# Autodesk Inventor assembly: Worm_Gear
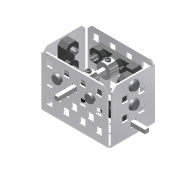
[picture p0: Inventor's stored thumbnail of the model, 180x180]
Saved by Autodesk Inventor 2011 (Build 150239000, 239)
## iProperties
Created: 2008-05
Part Number: Worm_Gear
Document SubType Name: Assembly
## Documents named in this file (8)
- C:\Data Folder\VEX 2011\Inventor Datasets\Unit 9\Worm_Gear.iam
- C:\Data Folder\VEX 2011\Inventor Datasets\Unit 9\Components\VL-WORM-BRK RevA.ipt
- C:\Data Folder\VEX 2011\Inventor Datasets\Unit 9\Components\BEARING-FLAT.ipt
- C:\Data Folder\VEX 2011\Inventor Datasets\Unit 9\Components\BEARING-RIVET.ipt
- C:\Data Folder\VEX 2011\Inventor Datasets\Unit 9\Components\Shaft_Collar.iam
- C:\Data Folder\VEX 2011\Inventor Datasets\Unit 9\Components\SHAFT-2000.ipt
- C:\Data Folder\VEX 2011\Inventor Datasets\Unit 9\Components\SHAFT-3000.ipt
- C:\Data Folder\VEX 2011\Inventor Datasets\Unit 9\Components\SPACER-THIN.ipt
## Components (22 placed, 7 different names)
1. VL-WORM-BRK RevA:1 — Mate:1, Mate:2, Mate:3, Mate:4, Mate:5, Mate:6, Mate:7, Mate:8, Mate:9, Mate:10, Mate:11, Mate:12, Flush:1, Flush:2, Flush:3, Flush:4, Flush:5, Flush:6, Flush:7, Flush:8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
2. BEARING-FLAT:1 — Mate:1, Mate:2, Mate:3, Mate:13, Mate:14, Mate:27
3. BEARING-FLAT:2 — Mate:4, Mate:5, Mate:6, Mate:15, Mate:16, Mate:25, Mate:31
4. BEARING-FLAT:3 — Mate:7, Mate:8, Mate:9, Mate:17, Mate:18, Mate:21, Mate:24
5. BEARING-FLAT:4 — Mate:10, Mate:11, Mate:12, Mate:19, Mate:20
6. BEARING-RIVET:1 — Mate:13, Flush:1
7. BEARING-RIVET:2 — Mate:14, Flush:2
8. BEARING-RIVET:3 — Mate:17, Flush:5
9. BEARING-RIVET:4 — Mate:18, Flush:6
10. BEARING-RIVET:5 — Mate:15, Flush:3
11. BEARING-RIVET:6 — Mate:16, Flush:4
12. BEARING-RIVET:7 — Mate:19, Flush:7
13. BEARING-RIVET:8 — Mate:20, Flush:8
14. Shaft_Collar:1 [sub-assembly] — Mate:22, Angle:2
15. SHAFT-2000:1 — Mate:21, Flush:9, Angle:1, Mate:22, Mate:23
16. Shaft_Collar:2 [sub-assembly] — Mate:23, Angle:3, Mate:24, Angle:4
17. Shaft_Collar:4 [sub-assembly] — Mate:26, Mate:27, Angle:6, Mate:30
18. SHAFT-3000:1 — Mate:25, Flush:10, Angle:5, Mate:26, Mate:28, Mate:29, Mate:33, Mate:34
19. SPACER-THIN:1 — Mate:28, Mate:31, Mate:35
20. SPACER-THIN:2 — Mate:29, Mate:30
21. SPACER-THIN:3 — Mate:34, Mate:35, Mate:36
22. SPACER-THIN:4 — Mate:33, Mate:36
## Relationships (51: Mate 35, Flush 10, Angle 6)
- Mate:1: VL-WORM-BRK RevA:1 ↔ BEARING-FLAT:1
- Mate:2: VL-WORM-BRK RevA:1 ↔ BEARING-FLAT:1
- Mate:3: VL-WORM-BRK RevA:1 ↔ BEARING-FLAT:1
- Mate:4: VL-WORM-BRK RevA:1 ↔ BEARING-FLAT:2
- Mate:5: VL-WORM-BRK RevA:1 ↔ BEARING-FLAT:2
- Mate:6: VL-WORM-BRK RevA:1 ↔ BEARING-FLAT:2
- Mate:7: VL-WORM-BRK RevA:1 ↔ BEARING-FLAT:3
- Mate:8: VL-WORM-BRK RevA:1 ↔ BEARING-FLAT:3
- Mate:9: VL-WORM-BRK RevA:1 ↔ BEARING-FLAT:3
- Mate:10: VL-WORM-BRK RevA:1 ↔ BEARING-FLAT:4
- Mate:11: VL-WORM-BRK RevA:1 ↔ BEARING-FLAT:4
- Mate:12: VL-WORM-BRK RevA:1 ↔ BEARING-FLAT:4
- Mate:13: BEARING-FLAT:1 ↔ BEARING-RIVET:1
- Flush:1: VL-WORM-BRK RevA:1 ↔ BEARING-RIVET:1
- Mate:14: BEARING-FLAT:1 ↔ BEARING-RIVET:2
- Flush:2: VL-WORM-BRK RevA:1 ↔ BEARING-RIVET:2
- Mate:15: BEARING-FLAT:2 ↔ BEARING-RIVET:5
- Flush:3: VL-WORM-BRK RevA:1 ↔ BEARING-RIVET:5
- Mate:16: BEARING-FLAT:2 ↔ BEARING-RIVET:6
- Flush:4: VL-WORM-BRK RevA:1 ↔ BEARING-RIVET:6
- Mate:17: BEARING-FLAT:3 ↔ BEARING-RIVET:3
- Mate:18: BEARING-FLAT:3 ↔ BEARING-RIVET:4
- Mate:19: BEARING-FLAT:4 ↔ BEARING-RIVET:7
- Mate:20: BEARING-FLAT:4 ↔ BEARING-RIVET:8
- Flush:5: VL-WORM-BRK RevA:1 ↔ BEARING-RIVET:3
- Flush:6: VL-WORM-BRK RevA:1 ↔ BEARING-RIVET:4
- Flush:7: VL-WORM-BRK RevA:1 ↔ BEARING-RIVET:7
- Flush:8: VL-WORM-BRK RevA:1 ↔ BEARING-RIVET:8
- Mate:21: BEARING-FLAT:3 ↔ SHAFT-2000:1
- Flush:9: VL-WORM-BRK RevA:1 ↔ SHAFT-2000:1
- Angle:1: VL-WORM-BRK RevA:1 ↔ SHAFT-2000:1
- Mate:22: Shaft_Collar:1 ↔ SHAFT-2000:1
- Angle:2: VL-WORM-BRK RevA:1 ↔ Shaft_Collar:1
- Mate:23: SHAFT-2000:1 ↔ Shaft_Collar:2
- Angle:3: VL-WORM-BRK RevA:1 ↔ Shaft_Collar:2
- Mate:24: BEARING-FLAT:3 ↔ Shaft_Collar:2
- Angle:4: VL-WORM-BRK RevA:1 ↔ Shaft_Collar:2
- Mate:25: BEARING-FLAT:2 ↔ SHAFT-3000:1
- Flush:10: VL-WORM-BRK RevA:1 ↔ SHAFT-3000:1
- Angle:5: VL-WORM-BRK RevA:1 ↔ SHAFT-3000:1
- Mate:26: Shaft_Collar:4 ↔ SHAFT-3000:1
- Mate:27: BEARING-FLAT:1 ↔ Shaft_Collar:4
- Angle:6: VL-WORM-BRK RevA:1 ↔ Shaft_Collar:4
- Mate:28: SHAFT-3000:1 ↔ SPACER-THIN:1
- Mate:29: SHAFT-3000:1 ↔ SPACER-THIN:2
- Mate:30: Shaft_Collar:4 ↔ SPACER-THIN:2
- Mate:31: BEARING-FLAT:2 ↔ SPACER-THIN:1
- Mate:33: SHAFT-3000:1 ↔ SPACER-THIN:4
- Mate:34: SHAFT-3000:1 ↔ SPACER-THIN:3
- Mate:35: SPACER-THIN:1 ↔ SPACER-THIN:3
- Mate:36: SPACER-THIN:3 ↔ SPACER-THIN:4
